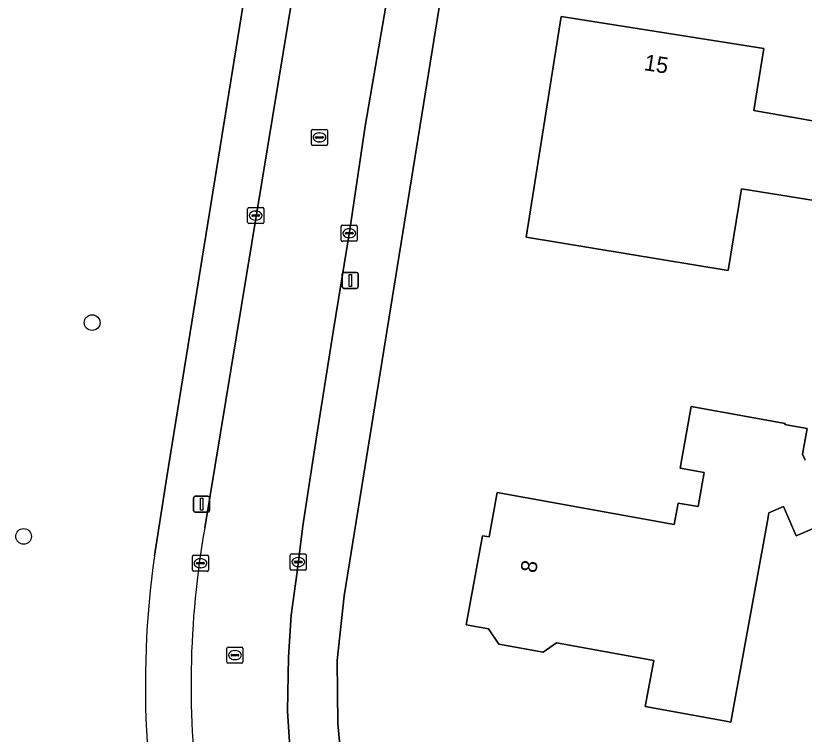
# Model space of a CAD drawing. Extents: x 161139 to 161601, y 381708 to 382245.
# Drawn here: x 161247.4 to 161296.54, y 381929.18 to 381973.95 of the extents above; entities that cross this region are included whole.
import ezdxf

# ---------------------------------------------------------------- set-up
doc = ezdxf.new("R2010")
doc.units = 0
for name, color, linetype in [('IMGEO_Boom', 7, 'Continuous'), ('IMGEO_Erf', 7, 'Continuous'), ('IMGEO_Groenvoorziening', 7, 'Continuous'), ('IMGEO_Kolk', 7, 'Continuous'), ('IMGEO_Lichtmast', 7, 'Continuous'), ('IMGEO_Pand', 7, 'Continuous'), ('IMGEO_Pand_nummerreeks', 7, 'Continuous'), ('IMGEO_Rijbaan_lokaal_open', 7, 'Continuous'), ('IMGEO_Rioolput', 7, 'Continuous'), ('IMGEO_Voetpad_open', 7, 'Continuous')]:
    doc.layers.add(name, color=color, linetype=linetype)

msp = doc.modelspace()

# ---------------------------------------------------------------- linework, layer by layer
at = {"layer": 'IMGEO_Boom'}
for centre in [(161252.16, 381954.829), (161247.888, 381941.507)]:
    msp.add_circle(centre, 0.489, dxfattribs=at)
at = {"layer": 'IMGEO_Erf'}
for points in [[(161370.462, 381928.258), (161276.309, 381989.126), (161276.14, 381989.025), (161267.873, 381937.797), (161267.435, 381933.784), (161267.467, 381929.855), (161267.871, 381925.589), (161268.634, 381921.624), (161269.796, 381917.444), (161271.533, 381912.948), (161272.783, 381910.378), (161277.045, 381903.774)], [(161298.211, 381942.48), (161296.04, 381941.544), (161295.252, 381943.372), (161294.338, 381942.978), (161294.265, 381942.576), (161291.973, 381929.937), (161291.557, 381930.012), (161286.637, 381930.904), (161287.158, 381933.774), (161281.107, 381934.871), (161280.27, 381934.291), (161277.515, 381934.791), (161276.858, 381935.739), (161275.471, 381935.99), (161276.48, 381941.554), (161276.904, 381941.479), (161277.407, 381944.254), (161288.438, 381942.254), (161288.68, 381943.588), (161289.928, 381943.362), (161290.314, 381945.493), (161288.805, 381945.766), (161289.501, 381949.607), (161295.347, 381948.546), (161295.334, 381948.474), (161295.664, 381948.413), (161296.72, 381948.236), (161296.441, 381946.64), (161296.607, 381946.251)]]:
    msp.add_lwpolyline(points, dxfattribs=at)
msp.add_lwpolyline([(161291.811, 381958.087), (161279.219, 381960.153), (161281.395, 381973.911), (161294.018, 381971.914), (161293.408, 381968.055), (161299.194, 381967.02), (161298.451, 381962.239), (161292.636, 381963.173)], close=True, dxfattribs=at)
at = {"layer": 'IMGEO_Groenvoorziening'}
msp.add_lwpolyline([(161256.038, 381940.3), (161256.817, 381945.219), (161264.337, 381991.77), (161264.343, 381991.806), (161265.667, 382000), (161266.948, 382007.917), (161254.667, 382014.822), (161253.816, 382015.301)], dxfattribs=at)
msp.add_arc((161314.162, 381932.197), 58.686, 172.06408, 194.77714, dxfattribs=at)
at = {"layer": 'IMGEO_Kolk'}
for p, q in [((161261.852, 381961.075), (161261.852, 381961.927)), ((161261.927, 381962.001), (161262.779, 381962.001)), ((161262.853, 381961.927), (161262.853, 381961.075)), ((161262.111, 381961.495), (161262.111, 381961.507)), ((161262.549, 381961.458), (161262.151, 381961.458)), ((161262.154, 381961.544), (161262.552, 381961.544)), ((161262.34, 381961.781), (161262.365, 381961.781)), ((161262.595, 381961.507), (161262.595, 381961.495)), ((161262.779, 381961.001), (161261.927, 381961.001)), ((161262.363, 381961.221), (161262.338, 381961.221)), ((161267.76, 381960.895), (161268.612, 381960.895)), ((161267.685, 381959.969), (161267.685, 381960.821)), ((161267.944, 381960.389), (161267.944, 381960.401)), ((161268.382, 381960.352), (161267.984, 381960.352)), ((161267.987, 381960.438), (161268.385, 381960.438)), ((161268.173, 381960.675), (161268.198, 381960.675)), ((161268.428, 381960.401), (161268.428, 381960.389)), ((161268.686, 381960.821), (161268.686, 381959.969)), ((161268.612, 381959.895), (161267.76, 381959.895)), ((161268.196, 381960.115), (161268.171, 381960.115)), ((161258.408, 381939.406), (161258.408, 381940.258)), ((161258.483, 381940.332), (161259.335, 381940.332)), ((161259.409, 381940.258), (161259.409, 381939.406)), ((161264.508, 381939.486), (161264.508, 381940.338)), ((161264.583, 381940.412), (161265.435, 381940.412)), ((161265.509, 381940.338), (161265.509, 381939.486)), ((161258.667, 381939.826), (161258.667, 381939.838)), ((161259.105, 381939.789), (161258.707, 381939.789)), ((161258.71, 381939.875), (161259.108, 381939.875)), ((161258.896, 381940.112), (161258.921, 381940.112)), ((161259.151, 381939.838), (161259.151, 381939.826)), ((161264.767, 381939.906), (161264.767, 381939.918)), ((161265.205, 381939.869), (161264.807, 381939.869)), ((161264.81, 381939.955), (161265.208, 381939.955)), ((161264.996, 381940.192), (161265.021, 381940.192)), ((161265.251, 381939.918), (161265.251, 381939.906)), ((161259.335, 381939.332), (161258.483, 381939.332)), ((161258.919, 381939.552), (161258.894, 381939.552)), ((161265.435, 381939.412), (161264.583, 381939.412)), ((161265.019, 381939.632), (161264.994, 381939.632))]:
    msp.add_line(p, q, dxfattribs=at)
for points in [[(161261.852, 381961.075), (161261.852, 381961.927)], [(161261.927, 381962.001), (161262.779, 381962.001)], [(161262.853, 381961.927), (161262.853, 381961.075)], [(161262.779, 381961.001), (161261.927, 381961.001)], [(161267.76, 381960.895), (161268.612, 381960.895)], [(161267.685, 381959.969), (161267.685, 381960.821)], [(161268.686, 381960.821), (161268.686, 381959.969)], [(161268.612, 381959.895), (161267.76, 381959.895)], [(161258.408, 381939.406), (161258.408, 381940.258)], [(161258.483, 381940.332), (161259.335, 381940.332)], [(161259.409, 381940.258), (161259.409, 381939.406)], [(161264.508, 381939.486), (161264.508, 381940.338)], [(161264.583, 381940.412), (161265.435, 381940.412)], [(161265.509, 381940.338), (161265.509, 381939.486)], [(161259.335, 381939.332), (161258.483, 381939.332)], [(161265.435, 381939.412), (161264.583, 381939.412)]]:
    msp.add_lwpolyline(points, dxfattribs=at)
for centre, radius, start, end in [((161261.929, 381961.925), 0.0765, 91.552, 178.448), ((161261.929, 381961.925), 0.0765, 91.552, 178.448), ((161262.777, 381961.925), 0.0765, 1.552, 88.448), ((161262.777, 381961.925), 0.0765, 1.552, 88.448), ((161262.151, 381961.504), 0.0403, 85.8775, 175.7526), ((161262.148, 381961.494), 0.0366, 178.938, 274.7102), ((161262.552, 381961.501), 0.043, 264.8664, 352.4533), ((161262.556, 381961.506), 0.0386, 1.7309, 96.639), ((161261.929, 381961.077), 0.0765, 181.552, 268.448), ((161261.929, 381961.077), 0.0765, 181.552, 268.448), ((161262.777, 381961.077), 0.0765, 271.552, 358.448), ((161262.777, 381961.077), 0.0765, 271.552, 358.448), ((161267.762, 381960.819), 0.0765, 91.552, 178.448), ((161267.762, 381960.819), 0.0765, 91.552, 178.448), ((161268.61, 381960.819), 0.0765, 1.552, 88.448), ((161268.61, 381960.819), 0.0765, 1.552, 88.448), ((161267.984, 381960.398), 0.0403, 85.8775, 175.7526), ((161267.981, 381960.388), 0.0366, 178.938, 274.7102), ((161268.385, 381960.395), 0.043, 264.8664, 352.4533), ((161268.389, 381960.4), 0.0386, 1.7309, 96.639), ((161267.762, 381959.971), 0.0765, 181.552, 268.448), ((161267.762, 381959.971), 0.0765, 181.552, 268.448), ((161268.61, 381959.971), 0.0765, 271.552, 358.448), ((161268.61, 381959.971), 0.0765, 271.552, 358.448), ((161258.485, 381940.256), 0.0765, 91.552, 178.448), ((161258.485, 381940.256), 0.0765, 91.552, 178.448), ((161259.333, 381940.256), 0.0765, 1.552, 88.448), ((161259.333, 381940.256), 0.0765, 1.552, 88.448), ((161264.585, 381940.336), 0.0765, 91.552, 178.448), ((161264.585, 381940.336), 0.0765, 91.552, 178.448), ((161265.433, 381940.336), 0.0765, 1.552, 88.448), ((161265.433, 381940.336), 0.0765, 1.552, 88.448), ((161258.707, 381939.835), 0.0403, 85.8775, 175.7526), ((161258.704, 381939.825), 0.0366, 178.938, 274.7102), ((161259.108, 381939.832), 0.043, 264.8664, 352.4533), ((161259.112, 381939.837), 0.0386, 1.7309, 96.639), ((161264.807, 381939.915), 0.0403, 85.8775, 175.7526), ((161264.804, 381939.905), 0.0366, 178.938, 274.7102), ((161265.208, 381939.912), 0.043, 264.8664, 352.4533), ((161265.212, 381939.917), 0.0386, 1.7309, 96.639), ((161258.485, 381939.408), 0.0765, 181.552, 268.448), ((161258.485, 381939.408), 0.0765, 181.552, 268.448), ((161259.333, 381939.408), 0.0765, 271.552, 358.448), ((161259.333, 381939.408), 0.0765, 271.552, 358.448), ((161264.585, 381939.488), 0.0765, 181.552, 268.448), ((161264.585, 381939.488), 0.0765, 181.552, 268.448), ((161265.433, 381939.488), 0.0765, 271.552, 358.448), ((161265.433, 381939.488), 0.0765, 271.552, 358.448)]:
    msp.add_arc(centre, radius, start, end, dxfattribs=at)
for centre, major_axis, ratio, start_param, end_param in [((161262.339, 381961.501), (-0.387, 0.002), 0.722429, 4.712389, 7.853982), ((161262.364, 381961.501), (-0.39, 0.002), 0.717154, 1.570796, 4.712389), ((161268.172, 381960.395), (-0.387, 0.002), 0.722429, 4.712389, 7.853982), ((161268.197, 381960.395), (-0.39, 0.002), 0.717154, 1.570796, 4.712389), ((161258.895, 381939.832), (-0.387, 0.002), 0.722429, 4.712389, 7.853982), ((161258.92, 381939.832), (-0.39, 0.002), 0.717154, 1.570796, 4.712389), ((161264.995, 381939.912), (-0.387, 0.002), 0.722429, 4.712389, 7.853982), ((161265.02, 381939.912), (-0.39, 0.002), 0.717154, 1.570796, 4.712389)]:
    msp.add_ellipse(centre, major_axis=major_axis, ratio=ratio, start_param=start_param, end_param=end_param, dxfattribs=at)
at = {"layer": 'IMGEO_Lichtmast'}
for p, q in [((161267.85, 381957.961), (161268.64, 381957.961)), ((161268.64, 381957.961), (161267.85, 381957.961)), ((161267.75, 381957.061), (161267.75, 381957.861)), ((161267.75, 381957.861), (161267.75, 381957.061)), ((161268.74, 381957.861), (161268.74, 381957.061)), ((161268.74, 381957.061), (161268.74, 381957.861)), ((161268.64, 381956.961), (161267.85, 381956.961)), ((161267.85, 381956.961), (161268.64, 381956.961)), ((161258.483, 381943.11), (161258.483, 381943.91)), ((161258.483, 381943.91), (161258.483, 381943.11)), ((161258.583, 381944.01), (161259.373, 381944.01)), ((161259.373, 381944.01), (161258.583, 381944.01)), ((161259.473, 381943.91), (161259.473, 381943.11)), ((161259.473, 381943.11), (161259.473, 381943.91)), ((161259.373, 381943.01), (161258.583, 381943.01)), ((161258.583, 381943.01), (161259.373, 381943.01))]:
    msp.add_line(p, q, dxfattribs=at)
for points in [[(161268.17, 381957.836), (161268.32, 381957.836), (161268.32, 381957.086), (161268.17, 381957.086), (161268.17, 381957.836)], [(161258.903, 381943.885), (161259.053, 381943.885), (161259.053, 381943.135), (161258.903, 381943.135), (161258.903, 381943.885)]]:
    msp.add_lwpolyline(points, dxfattribs=at)
for centre, start, end in [((161267.85, 381957.861), 90, 180), ((161267.85, 381957.861), 90, 180), ((161268.64, 381957.861), 0, 90), ((161268.64, 381957.861), 360, 90), ((161267.85, 381957.061), 180, 270), ((161267.85, 381957.061), 180, 270), ((161268.64, 381957.061), 270, 0), ((161268.64, 381957.061), 270, 0), ((161258.583, 381943.91), 90, 180), ((161258.583, 381943.91), 90, 180), ((161259.373, 381943.91), 0, 90), ((161259.373, 381943.91), 360, 90), ((161258.583, 381943.11), 180, 270), ((161258.583, 381943.11), 180, 270), ((161259.373, 381943.11), 270, 0), ((161259.373, 381943.11), 270, 0)]:
    msp.add_arc(centre, 0.1, start, end, dxfattribs=at)
at = {"layer": 'IMGEO_Pand'}
msp.add_lwpolyline([(161294.018, 381971.914), (161281.395, 381973.911), (161279.219, 381960.153), (161291.811, 381958.087), (161292.636, 381963.173), (161298.451, 381962.239), (161299.194, 381967.02), (161293.408, 381968.055)], close=True, dxfattribs=at)
msp.add_lwpolyline([(161296.607, 381946.251), (161296.441, 381946.64), (161296.72, 381948.236), (161295.664, 381948.413), (161295.334, 381948.474), (161295.347, 381948.546), (161289.501, 381949.607), (161288.805, 381945.766), (161290.314, 381945.493), (161289.928, 381943.362), (161288.68, 381943.588), (161288.438, 381942.254), (161277.407, 381944.254), (161276.904, 381941.479), (161276.48, 381941.554), (161275.471, 381935.99), (161276.858, 381935.739), (161277.515, 381934.791), (161280.27, 381934.291), (161281.107, 381934.871), (161287.158, 381933.774), (161286.637, 381930.904), (161291.557, 381930.012), (161291.973, 381929.937), (161294.265, 381942.576), (161294.338, 381942.978), (161295.252, 381943.372), (161296.04, 381941.544), (161298.211, 381942.48)], dxfattribs=at)
at = {"layer": 'IMGEO_Rijbaan_lokaal_open'}
msp.add_lwpolyline([(161265.564, 381921.601), (161265, 381924.596), (161264.526, 381927.722), (161264.331, 381930.62), (161264.405, 381933.991), (161264.554, 381936.602), (161264.932, 381939.304), (161265.288, 381942.157), (161265.934, 381946.371), (161266.311, 381948.744), (161267.185, 381954.246), (161268.219, 381960.609), (161269.186, 381967.075), (161270.456, 381974.554), (161271.16, 381978.342), (161273.075, 381989.612), (161273.208, 381990.334), (161267.316, 381991.303), (161259.178, 381942.049)], dxfattribs=at)
msp.add_arc((161315.125, 381932.225), 56.803, 170.0404, 187.9434, dxfattribs=at)
at = {"layer": 'IMGEO_Rioolput'}
for p, q in [((161265.827, 381965.947), (161265.827, 381966.799)), ((161265.902, 381966.873), (161266.754, 381966.873)), ((161266.828, 381966.799), (161266.828, 381965.947)), ((161266.086, 381966.367), (161266.086, 381966.379)), ((161266.524, 381966.33), (161266.126, 381966.33)), ((161266.129, 381966.416), (161266.527, 381966.416)), ((161266.315, 381966.653), (161266.34, 381966.653)), ((161266.57, 381966.379), (161266.57, 381966.367)), ((161266.754, 381965.873), (161265.902, 381965.873)), ((161266.338, 381966.093), (161266.313, 381966.093)), ((161260.56, 381933.683), (161260.56, 381934.535)), ((161260.635, 381934.609), (161261.487, 381934.609)), ((161261.048, 381934.389), (161261.073, 381934.389)), ((161261.561, 381934.535), (161261.561, 381933.683)), ((161260.819, 381934.103), (161260.819, 381934.115)), ((161261.257, 381934.066), (161260.859, 381934.066)), ((161260.862, 381934.152), (161261.26, 381934.152)), ((161261.071, 381933.829), (161261.046, 381933.829)), ((161261.303, 381934.115), (161261.303, 381934.103)), ((161261.487, 381933.609), (161260.635, 381933.609))]:
    msp.add_line(p, q, dxfattribs=at)
for points in [[(161265.827, 381965.947), (161265.827, 381966.799)], [(161265.902, 381966.873), (161266.754, 381966.873)], [(161266.828, 381966.799), (161266.828, 381965.947)], [(161266.754, 381965.873), (161265.902, 381965.873)], [(161260.56, 381933.683), (161260.56, 381934.535)], [(161260.635, 381934.609), (161261.487, 381934.609)], [(161261.561, 381934.535), (161261.561, 381933.683)], [(161261.487, 381933.609), (161260.635, 381933.609)]]:
    msp.add_lwpolyline(points, dxfattribs=at)
for centre, radius, start, end in [((161265.904, 381966.797), 0.0765, 91.552, 178.448), ((161265.904, 381966.797), 0.0765, 91.552, 178.448), ((161266.752, 381966.797), 0.0765, 1.552, 88.448), ((161266.752, 381966.797), 0.0765, 1.552, 88.448), ((161266.126, 381966.376), 0.0403, 85.8775, 175.7526), ((161266.123, 381966.366), 0.0366, 178.938, 274.7102), ((161266.527, 381966.373), 0.043, 264.8664, 352.4533), ((161266.531, 381966.378), 0.0386, 1.7309, 96.639), ((161265.904, 381965.949), 0.0765, 181.552, 268.448), ((161265.904, 381965.949), 0.0765, 181.552, 268.448), ((161266.752, 381965.949), 0.0765, 271.552, 358.448), ((161266.752, 381965.949), 0.0765, 271.552, 358.448), ((161260.637, 381934.533), 0.0765, 91.552, 178.448), ((161260.637, 381934.533), 0.0765, 91.552, 178.448), ((161261.485, 381934.533), 0.0765, 1.552, 88.448), ((161261.485, 381934.533), 0.0765, 1.552, 88.448), ((161260.859, 381934.112), 0.0403, 85.8775, 175.7526), ((161260.856, 381934.102), 0.0366, 178.938, 274.7102), ((161261.26, 381934.109), 0.043, 264.8664, 352.4533), ((161261.264, 381934.114), 0.0386, 1.7309, 96.639), ((161260.637, 381933.685), 0.0765, 181.552, 268.448), ((161260.637, 381933.685), 0.0765, 181.552, 268.448), ((161261.485, 381933.685), 0.0765, 271.552, 358.448), ((161261.485, 381933.685), 0.0765, 271.552, 358.448)]:
    msp.add_arc(centre, radius, start, end, dxfattribs=at)
for centre, major_axis, ratio, start_param, end_param in [((161266.314, 381966.373), (-0.387, 0.002), 0.722429, 4.712389, 7.853982), ((161266.339, 381966.373), (-0.39, 0.002), 0.717154, 1.570796, 4.712389), ((161261.047, 381934.109), (-0.387, 0.002), 0.722429, 4.712389, 7.853982), ((161261.072, 381934.109), (-0.39, 0.002), 0.717154, 1.570796, 4.712389)]:
    msp.add_ellipse(centre, major_axis=major_axis, ratio=ratio, start_param=start_param, end_param=end_param, dxfattribs=at)
at = {"layer": 'IMGEO_Voetpad_open'}
for points in [[(161259.178, 381942.049), (161267.316, 381991.303), (161264.337, 381991.77), (161256.817, 381945.219), (161256.038, 381940.3)], [(161273.208, 381990.334), (161273.075, 381989.612), (161271.16, 381978.342), (161270.456, 381974.554), (161269.186, 381967.075), (161268.219, 381960.609), (161267.185, 381954.246), (161266.311, 381948.744), (161265.934, 381946.371), (161265.288, 381942.157), (161264.932, 381939.304), (161264.554, 381936.602), (161264.405, 381933.991), (161264.331, 381930.62), (161264.526, 381927.722), (161265, 381924.596), (161265.564, 381921.601), (161266.277, 381918.847), (161267.11, 381915.904), (161268.344, 381912.783), (161270.379, 381908.492), (161271.356, 381906.689)], [(161277.045, 381903.774), (161272.783, 381910.378), (161271.533, 381912.948), (161269.796, 381917.444), (161268.634, 381921.624), (161267.871, 381925.589), (161267.467, 381929.855), (161267.435, 381933.784), (161267.873, 381937.797), (161276.14, 381989.025)]]:
    msp.add_lwpolyline(points, dxfattribs=at)
for centre, radius, start, end in [((161315.125, 381932.225), 56.803, 170.0404, 187.9434), ((161314.162, 381932.197), 58.686, 172.06408, 194.77714)]:
    msp.add_arc(centre, radius, start, end, dxfattribs=at)

# ---------------------------------------------------------------- texts
at = {"layer": 'IMGEO_Pand_nummerreeks'}
for s, rotation, p in [('15', 351.0078, (161286.515, 381970.57)), ('8', 79.7271, (161279.822, 381939.185))]:
    msp.add_text(s, height=1, rotation=rotation, dxfattribs=at).set_placement(p)

doc.saveas('drawing.dxf')
